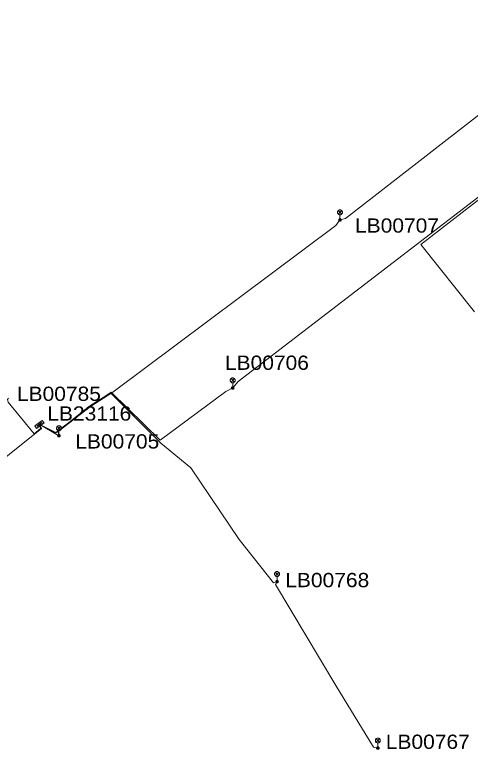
# Model space of a CAD drawing. Extents: x -688049 to -687261, y -973611 to -973038.
# Drawn here: x -687958.9 to -687889.6, y -973302.7 to -973190.9 of the extents above; entities that cross this region are included whole.
import ezdxf

# ---------------------------------------------------------------- set-up
doc = ezdxf.new("R2010")
doc.units = 0
doc.header["$LTSCALE"] = 0.87
doc.layers.add('1', color=7, linetype='Continuous', lineweight=13)

msp = doc.modelspace()

# ---------------------------------------------------------------- hatches: boundary and pattern name
at = {"layer": '1'}
for points in [[(-687955.848, -973253.491), (-687954.701, -973252.647), (-687954.42, -973253.03), (-687955.567, -973253.873)], [(-687955.506, -973253.475), (-687954.818, -973252.969), (-687954.762, -973253.045), (-687955.45, -973253.551)]]:
    msp.add_hatch(color=256, dxfattribs=at).paths.add_polyline_path(points)

# ---------------------------------------------------------------- linework, layer by layer
for p, q in [((-687909.715, -973220.745), (-687909.185, -973221.275)), ((-687909.715, -973221.275), (-687909.185, -973220.745)), ((-687909.45, -973222.16), (-687909.45, -973221.385)), ((-687926.015, -973246.305), (-687925.485, -973246.835)), ((-687926.015, -973246.835), (-687925.485, -973246.305)), ((-687925.75, -973247.72), (-687925.75, -973246.945)), ((-687955.105, -973253.298), (-687952.18, -973254.99)), ((-687952.445, -973253.575), (-687951.915, -973254.105)), ((-687952.445, -973254.105), (-687951.915, -973253.575)), ((-687952.18, -973254.99), (-687952.18, -973254.215)), ((-687919.275, -973275.765), (-687918.745, -973276.295)), ((-687919.275, -973276.295), (-687918.745, -973275.765)), ((-687919.01, -973277.18), (-687919.01, -973276.405)), ((-687903.955, -973301.075), (-687903.425, -973301.605)), ((-687903.955, -973301.605), (-687903.425, -973301.075)), ((-687903.69, -973302.49), (-687903.69, -973301.715))]:
    msp.add_line(p, q, dxfattribs=at)
for points in [[(-687909.45, -973222.16), (-687908.609, -973221.964), (-687869.535, -973191.59), (-687868.6, -973190.95)], [(-687925.75, -973247.72), (-687924.92, -973246.725), (-687887.835, -973218.267), (-687884.91, -973218.14)], [(-687884.91, -973218.14), (-687887.718, -973218.609), (-687897.147, -973225.919), (-687889.02, -973236.13)], [(-687952.18, -973254.99), (-687952.29, -973254.364), (-687947.369, -973250.548), (-687943.996, -973248.352), (-687910.065, -973223.036), (-687909.45, -973222.16)], [(-687925.75, -973247.72), (-687926.816, -973248.244), (-687936.782, -973255.65), (-687944.242, -973248.384), (-687947.425, -973250.503), (-687952.638, -973254.497), (-687955.105, -973253.298)], [(-687955.105, -973253.298), (-687952.625, -973254.568), (-687947.523, -973250.491), (-687946.412, -973249.8), (-687944.322, -973248.476), (-687936.678, -973256.094), (-687932.142, -973259.853), (-687924.795, -973270.781), (-687919.563, -973277.364), (-687919.01, -973277.18)], [(-687959.867, -973249.256), (-687959.977, -973249.491), (-687959.917, -973249.894), (-687955.919, -973254.677), (-687954.965, -973253.869), (-687955.105, -973253.298)], [(-687955.105, -973253.298), (-687954.813, -973253.904), (-687964.366, -973261.482), (-687966.646, -973263.218), (-687977.095, -973271.505), (-687977.93, -973272.313), (-687978.18, -973273.2)], [(-687919.01, -973277.18), (-687919.269, -973277.621), (-687910.066, -973293), (-687904.34, -973302.349), (-687903.69, -973302.49)]]:
    msp.add_lwpolyline(points, dxfattribs=at)
for points in [[(-687909.075, -973221.01), (-687909.081, -973220.945), (-687909.098, -973220.882), (-687909.125, -973220.822), (-687909.163, -973220.769), (-687909.209, -973220.723), (-687909.263, -973220.685), (-687909.322, -973220.658), (-687909.385, -973220.641), (-687909.45, -973220.635), (-687909.515, -973220.641), (-687909.578, -973220.658), (-687909.638, -973220.685), (-687909.691, -973220.723), (-687909.737, -973220.769), (-687909.775, -973220.822), (-687909.802, -973220.882), (-687909.819, -973220.945), (-687909.825, -973221.01), (-687909.819, -973221.075), (-687909.802, -973221.138), (-687909.775, -973221.198), (-687909.737, -973221.251), (-687909.691, -973221.297), (-687909.638, -973221.335), (-687909.578, -973221.362), (-687909.515, -973221.379), (-687909.45, -973221.385), (-687909.385, -973221.379), (-687909.322, -973221.362), (-687909.263, -973221.335), (-687909.209, -973221.297), (-687909.163, -973221.251), (-687909.125, -973221.198), (-687909.098, -973221.138), (-687909.081, -973221.075)], [(-687909.26, -973222.16), (-687909.263, -973222.127), (-687909.271, -973222.095), (-687909.285, -973222.065), (-687909.304, -973222.038), (-687909.328, -973222.014), (-687909.355, -973221.995), (-687909.385, -973221.981), (-687909.417, -973221.973), (-687909.45, -973221.97), (-687909.483, -973221.973), (-687909.515, -973221.981), (-687909.545, -973221.995), (-687909.572, -973222.014), (-687909.596, -973222.038), (-687909.615, -973222.065), (-687909.629, -973222.095), (-687909.637, -973222.127), (-687909.64, -973222.16), (-687909.637, -973222.193), (-687909.629, -973222.225), (-687909.615, -973222.255), (-687909.596, -973222.282), (-687909.572, -973222.306), (-687909.545, -973222.325), (-687909.515, -973222.339), (-687909.483, -973222.347), (-687909.45, -973222.35), (-687909.417, -973222.347), (-687909.385, -973222.339), (-687909.355, -973222.325), (-687909.328, -973222.306), (-687909.304, -973222.282), (-687909.285, -973222.255), (-687909.271, -973222.225), (-687909.263, -973222.193)], [(-687909.4, -973222.16), (-687909.401, -973222.151), (-687909.403, -973222.143), (-687909.407, -973222.135), (-687909.412, -973222.128), (-687909.418, -973222.122), (-687909.425, -973222.117), (-687909.433, -973222.113), (-687909.441, -973222.111), (-687909.45, -973222.11), (-687909.459, -973222.111), (-687909.467, -973222.113), (-687909.475, -973222.117), (-687909.482, -973222.122), (-687909.488, -973222.128), (-687909.493, -973222.135), (-687909.497, -973222.143), (-687909.499, -973222.151), (-687909.5, -973222.16), (-687909.499, -973222.169), (-687909.497, -973222.177), (-687909.493, -973222.185), (-687909.488, -973222.192), (-687909.482, -973222.198), (-687909.475, -973222.203), (-687909.467, -973222.207), (-687909.459, -973222.209), (-687909.45, -973222.21), (-687909.441, -973222.209), (-687909.433, -973222.207), (-687909.425, -973222.203), (-687909.418, -973222.198), (-687909.412, -973222.192), (-687909.407, -973222.185), (-687909.403, -973222.177), (-687909.401, -973222.169)], [(-687925.375, -973246.57), (-687925.381, -973246.505), (-687925.398, -973246.442), (-687925.425, -973246.383), (-687925.463, -973246.329), (-687925.509, -973246.283), (-687925.562, -973246.245), (-687925.622, -973246.218), (-687925.685, -973246.201), (-687925.75, -973246.195), (-687925.815, -973246.201), (-687925.878, -973246.218), (-687925.938, -973246.245), (-687925.991, -973246.283), (-687926.037, -973246.329), (-687926.075, -973246.383), (-687926.102, -973246.442), (-687926.119, -973246.505), (-687926.125, -973246.57), (-687926.119, -973246.635), (-687926.102, -973246.698), (-687926.075, -973246.758), (-687926.037, -973246.811), (-687925.991, -973246.857), (-687925.938, -973246.895), (-687925.878, -973246.922), (-687925.815, -973246.939), (-687925.75, -973246.945), (-687925.685, -973246.939), (-687925.622, -973246.922), (-687925.562, -973246.895), (-687925.509, -973246.857), (-687925.463, -973246.811), (-687925.425, -973246.758), (-687925.398, -973246.698), (-687925.381, -973246.635)], [(-687925.56, -973247.72), (-687925.563, -973247.687), (-687925.571, -973247.655), (-687925.585, -973247.625), (-687925.604, -973247.598), (-687925.628, -973247.574), (-687925.655, -973247.555), (-687925.685, -973247.541), (-687925.717, -973247.533), (-687925.75, -973247.53), (-687925.783, -973247.533), (-687925.815, -973247.541), (-687925.845, -973247.555), (-687925.872, -973247.574), (-687925.896, -973247.598), (-687925.915, -973247.625), (-687925.929, -973247.655), (-687925.937, -973247.687), (-687925.94, -973247.72), (-687925.937, -973247.753), (-687925.929, -973247.785), (-687925.915, -973247.815), (-687925.896, -973247.842), (-687925.872, -973247.866), (-687925.845, -973247.885), (-687925.815, -973247.899), (-687925.783, -973247.907), (-687925.75, -973247.91), (-687925.717, -973247.907), (-687925.685, -973247.899), (-687925.655, -973247.885), (-687925.628, -973247.866), (-687925.604, -973247.842), (-687925.585, -973247.815), (-687925.571, -973247.785), (-687925.563, -973247.753)], [(-687925.7, -973247.72), (-687925.701, -973247.711), (-687925.703, -973247.703), (-687925.707, -973247.695), (-687925.712, -973247.688), (-687925.718, -973247.682), (-687925.725, -973247.677), (-687925.733, -973247.673), (-687925.741, -973247.671), (-687925.75, -973247.67), (-687925.759, -973247.671), (-687925.767, -973247.673), (-687925.775, -973247.677), (-687925.782, -973247.682), (-687925.788, -973247.688), (-687925.793, -973247.695), (-687925.797, -973247.703), (-687925.799, -973247.711), (-687925.8, -973247.72), (-687925.799, -973247.729), (-687925.797, -973247.737), (-687925.793, -973247.745), (-687925.788, -973247.752), (-687925.782, -973247.758), (-687925.775, -973247.763), (-687925.767, -973247.767), (-687925.759, -973247.769), (-687925.75, -973247.77), (-687925.741, -973247.769), (-687925.733, -973247.767), (-687925.725, -973247.763), (-687925.718, -973247.758), (-687925.712, -973247.752), (-687925.707, -973247.745), (-687925.703, -973247.737), (-687925.701, -973247.729)], [(-687955.848, -973253.491), (-687954.701, -973252.647), (-687954.42, -973253.03), (-687955.567, -973253.873)], [(-687955.848, -973253.491), (-687954.701, -973252.647), (-687954.42, -973253.03), (-687955.567, -973253.873)], [(-687955.506, -973253.475), (-687954.818, -973252.969), (-687954.762, -973253.045), (-687955.45, -973253.551)], [(-687951.805, -973253.84), (-687951.811, -973253.775), (-687951.828, -973253.712), (-687951.855, -973253.653), (-687951.893, -973253.599), (-687951.939, -973253.553), (-687951.992, -973253.515), (-687952.052, -973253.488), (-687952.115, -973253.471), (-687952.18, -973253.465), (-687952.245, -973253.471), (-687952.308, -973253.488), (-687952.368, -973253.515), (-687952.421, -973253.553), (-687952.467, -973253.599), (-687952.505, -973253.653), (-687952.532, -973253.712), (-687952.549, -973253.775), (-687952.555, -973253.84), (-687952.549, -973253.905), (-687952.532, -973253.968), (-687952.505, -973254.028), (-687952.467, -973254.081), (-687952.421, -973254.127), (-687952.368, -973254.165), (-687952.308, -973254.192), (-687952.245, -973254.209), (-687952.18, -973254.215), (-687952.115, -973254.209), (-687952.052, -973254.192), (-687951.992, -973254.165), (-687951.939, -973254.127), (-687951.893, -973254.081), (-687951.855, -973254.028), (-687951.828, -973253.968), (-687951.811, -973253.905)], [(-687951.99, -973254.99), (-687951.993, -973254.957), (-687952.001, -973254.925), (-687952.015, -973254.895), (-687952.034, -973254.868), (-687952.058, -973254.844), (-687952.085, -973254.825), (-687952.115, -973254.811), (-687952.147, -973254.803), (-687952.18, -973254.8), (-687952.213, -973254.803), (-687952.245, -973254.811), (-687952.275, -973254.825), (-687952.302, -973254.844), (-687952.326, -973254.868), (-687952.345, -973254.895), (-687952.359, -973254.925), (-687952.367, -973254.957), (-687952.37, -973254.99), (-687952.367, -973255.023), (-687952.359, -973255.055), (-687952.345, -973255.085), (-687952.326, -973255.112), (-687952.302, -973255.136), (-687952.275, -973255.155), (-687952.245, -973255.169), (-687952.213, -973255.177), (-687952.18, -973255.18), (-687952.147, -973255.177), (-687952.115, -973255.169), (-687952.085, -973255.155), (-687952.058, -973255.136), (-687952.034, -973255.112), (-687952.015, -973255.085), (-687952.001, -973255.055), (-687951.993, -973255.023)], [(-687952.13, -973254.99), (-687952.131, -973254.981), (-687952.133, -973254.973), (-687952.137, -973254.965), (-687952.142, -973254.958), (-687952.148, -973254.952), (-687952.155, -973254.947), (-687952.163, -973254.943), (-687952.171, -973254.941), (-687952.18, -973254.94), (-687952.189, -973254.941), (-687952.197, -973254.943), (-687952.205, -973254.947), (-687952.212, -973254.952), (-687952.218, -973254.958), (-687952.223, -973254.965), (-687952.227, -973254.973), (-687952.229, -973254.981), (-687952.23, -973254.99), (-687952.229, -973254.999), (-687952.227, -973255.007), (-687952.223, -973255.015), (-687952.218, -973255.022), (-687952.212, -973255.028), (-687952.205, -973255.033), (-687952.197, -973255.037), (-687952.189, -973255.039), (-687952.18, -973255.04), (-687952.171, -973255.039), (-687952.163, -973255.037), (-687952.155, -973255.033), (-687952.148, -973255.028), (-687952.142, -973255.022), (-687952.137, -973255.015), (-687952.133, -973255.007), (-687952.131, -973254.999)], [(-687918.635, -973276.03), (-687918.641, -973275.965), (-687918.658, -973275.902), (-687918.685, -973275.842), (-687918.723, -973275.789), (-687918.769, -973275.743), (-687918.822, -973275.705), (-687918.882, -973275.678), (-687918.945, -973275.661), (-687919.01, -973275.655), (-687919.075, -973275.661), (-687919.138, -973275.678), (-687919.198, -973275.705), (-687919.251, -973275.743), (-687919.297, -973275.789), (-687919.335, -973275.842), (-687919.362, -973275.902), (-687919.379, -973275.965), (-687919.385, -973276.03), (-687919.379, -973276.095), (-687919.362, -973276.158), (-687919.335, -973276.218), (-687919.297, -973276.271), (-687919.251, -973276.317), (-687919.198, -973276.355), (-687919.138, -973276.382), (-687919.075, -973276.399), (-687919.01, -973276.405), (-687918.945, -973276.399), (-687918.882, -973276.382), (-687918.822, -973276.355), (-687918.769, -973276.317), (-687918.723, -973276.271), (-687918.685, -973276.218), (-687918.658, -973276.158), (-687918.641, -973276.095)], [(-687918.82, -973277.18), (-687918.823, -973277.147), (-687918.831, -973277.115), (-687918.845, -973277.085), (-687918.864, -973277.058), (-687918.888, -973277.034), (-687918.915, -973277.015), (-687918.945, -973277.001), (-687918.977, -973276.993), (-687919.01, -973276.99), (-687919.043, -973276.993), (-687919.075, -973277.001), (-687919.105, -973277.015), (-687919.132, -973277.034), (-687919.156, -973277.058), (-687919.175, -973277.085), (-687919.189, -973277.115), (-687919.197, -973277.147), (-687919.2, -973277.18), (-687919.197, -973277.213), (-687919.189, -973277.245), (-687919.175, -973277.275), (-687919.156, -973277.302), (-687919.132, -973277.326), (-687919.105, -973277.345), (-687919.075, -973277.359), (-687919.043, -973277.367), (-687919.01, -973277.37), (-687918.977, -973277.367), (-687918.945, -973277.359), (-687918.915, -973277.345), (-687918.888, -973277.326), (-687918.864, -973277.302), (-687918.845, -973277.275), (-687918.831, -973277.245), (-687918.823, -973277.213)], [(-687918.96, -973277.18), (-687918.961, -973277.171), (-687918.963, -973277.163), (-687918.967, -973277.155), (-687918.972, -973277.148), (-687918.978, -973277.142), (-687918.985, -973277.137), (-687918.993, -973277.133), (-687919.001, -973277.131), (-687919.01, -973277.13), (-687919.019, -973277.131), (-687919.027, -973277.133), (-687919.035, -973277.137), (-687919.042, -973277.142), (-687919.048, -973277.148), (-687919.053, -973277.155), (-687919.057, -973277.163), (-687919.059, -973277.171), (-687919.06, -973277.18), (-687919.059, -973277.189), (-687919.057, -973277.197), (-687919.053, -973277.205), (-687919.048, -973277.212), (-687919.042, -973277.218), (-687919.035, -973277.223), (-687919.027, -973277.227), (-687919.019, -973277.229), (-687919.01, -973277.23), (-687919.001, -973277.229), (-687918.993, -973277.227), (-687918.985, -973277.223), (-687918.978, -973277.218), (-687918.972, -973277.212), (-687918.967, -973277.205), (-687918.963, -973277.197), (-687918.961, -973277.189)], [(-687903.315, -973301.34), (-687903.321, -973301.275), (-687903.338, -973301.212), (-687903.365, -973301.153), (-687903.403, -973301.099), (-687903.449, -973301.053), (-687903.503, -973301.015), (-687903.562, -973300.988), (-687903.625, -973300.971), (-687903.69, -973300.965), (-687903.755, -973300.971), (-687903.818, -973300.988), (-687903.878, -973301.015), (-687903.931, -973301.053), (-687903.977, -973301.099), (-687904.015, -973301.153), (-687904.042, -973301.212), (-687904.059, -973301.275), (-687904.065, -973301.34), (-687904.059, -973301.405), (-687904.042, -973301.468), (-687904.015, -973301.528), (-687903.977, -973301.581), (-687903.931, -973301.627), (-687903.878, -973301.665), (-687903.818, -973301.692), (-687903.755, -973301.709), (-687903.69, -973301.715), (-687903.625, -973301.709), (-687903.562, -973301.692), (-687903.503, -973301.665), (-687903.449, -973301.627), (-687903.403, -973301.581), (-687903.365, -973301.528), (-687903.338, -973301.468), (-687903.321, -973301.405)], [(-687903.5, -973302.49), (-687903.503, -973302.457), (-687903.511, -973302.425), (-687903.525, -973302.395), (-687903.544, -973302.368), (-687903.568, -973302.344), (-687903.595, -973302.325), (-687903.625, -973302.311), (-687903.657, -973302.303), (-687903.69, -973302.3), (-687903.723, -973302.303), (-687903.755, -973302.311), (-687903.785, -973302.325), (-687903.812, -973302.344), (-687903.836, -973302.368), (-687903.855, -973302.395), (-687903.869, -973302.425), (-687903.877, -973302.457), (-687903.88, -973302.49), (-687903.877, -973302.523), (-687903.869, -973302.555), (-687903.855, -973302.585), (-687903.836, -973302.612), (-687903.812, -973302.636), (-687903.785, -973302.655), (-687903.755, -973302.669), (-687903.723, -973302.677), (-687903.69, -973302.68), (-687903.657, -973302.677), (-687903.625, -973302.669), (-687903.595, -973302.655), (-687903.568, -973302.636), (-687903.544, -973302.612), (-687903.525, -973302.585), (-687903.511, -973302.555), (-687903.503, -973302.523)], [(-687903.64, -973302.49), (-687903.641, -973302.481), (-687903.643, -973302.473), (-687903.647, -973302.465), (-687903.652, -973302.458), (-687903.658, -973302.452), (-687903.665, -973302.447), (-687903.673, -973302.443), (-687903.681, -973302.441), (-687903.69, -973302.44), (-687903.699, -973302.441), (-687903.707, -973302.443), (-687903.715, -973302.447), (-687903.722, -973302.452), (-687903.728, -973302.458), (-687903.733, -973302.465), (-687903.737, -973302.473), (-687903.739, -973302.481), (-687903.74, -973302.49), (-687903.739, -973302.499), (-687903.737, -973302.507), (-687903.733, -973302.515), (-687903.728, -973302.522), (-687903.722, -973302.528), (-687903.715, -973302.533), (-687903.707, -973302.537), (-687903.699, -973302.539), (-687903.69, -973302.54), (-687903.681, -973302.539), (-687903.673, -973302.537), (-687903.665, -973302.533), (-687903.658, -973302.528), (-687903.652, -973302.522), (-687903.647, -973302.515), (-687903.643, -973302.507), (-687903.641, -973302.499)]]:
    msp.add_lwpolyline(points, close=True, dxfattribs=at)

# ---------------------------------------------------------------- texts
at = {"layer": '1', "width": 1.1}
for s, height, p in [('LB00707', 2.167, (-687907.159, -973224.1)), ('LB00706', 2.167, (-687926.936, -973244.966)), ('LB00785', 2.167, (-687958.56, -973249.69)), ('LB23116', 2.168, (-687953.947, -973252.69)), ('LB00705', 2.167, (-687949.688, -973256.934)), ('LB00768', 2.167, (-687917.764, -973278.021)), ('LB00767', 2.167, (-687902.479, -973302.615))]:
    msp.add_text(s, height=height, dxfattribs=at).set_placement(p)

doc.saveas('drawing.dxf')
